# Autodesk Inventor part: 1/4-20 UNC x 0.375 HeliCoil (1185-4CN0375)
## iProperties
Title: 1/4-20 UNC x 0.375 HeliCoil (1185-4CN0375)
Author: CFitzwater
Shininess: 64.0
Angle Display Precision: 2
Document Length Units: 11272
Document Angle Units: 11286
Document Time Units: 11279
Document Mass Units: 11290
Document Length Units Precision: 3
Document Angle Units Precision: 2
Compacted: True
PropertySet Name: _Private Model Information
Created: 2002-02
Part Number: Helicoil-1185-CN-NoOD
Material: Stainless Steel, Austenitic
Document SubType Name: Modeling
Designer: CFitzwater
Control State: 0
Master: False
Checked Out: False
PropertySet Name: Design Tracking Control
Density: 7.750000000000001
Volumn: 0.37239295650448834
Area: 5.5389113408432396
PropertySet Name: Model Information
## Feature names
1. Extrusion1
2. Chamfer1
3. Chamfer2
